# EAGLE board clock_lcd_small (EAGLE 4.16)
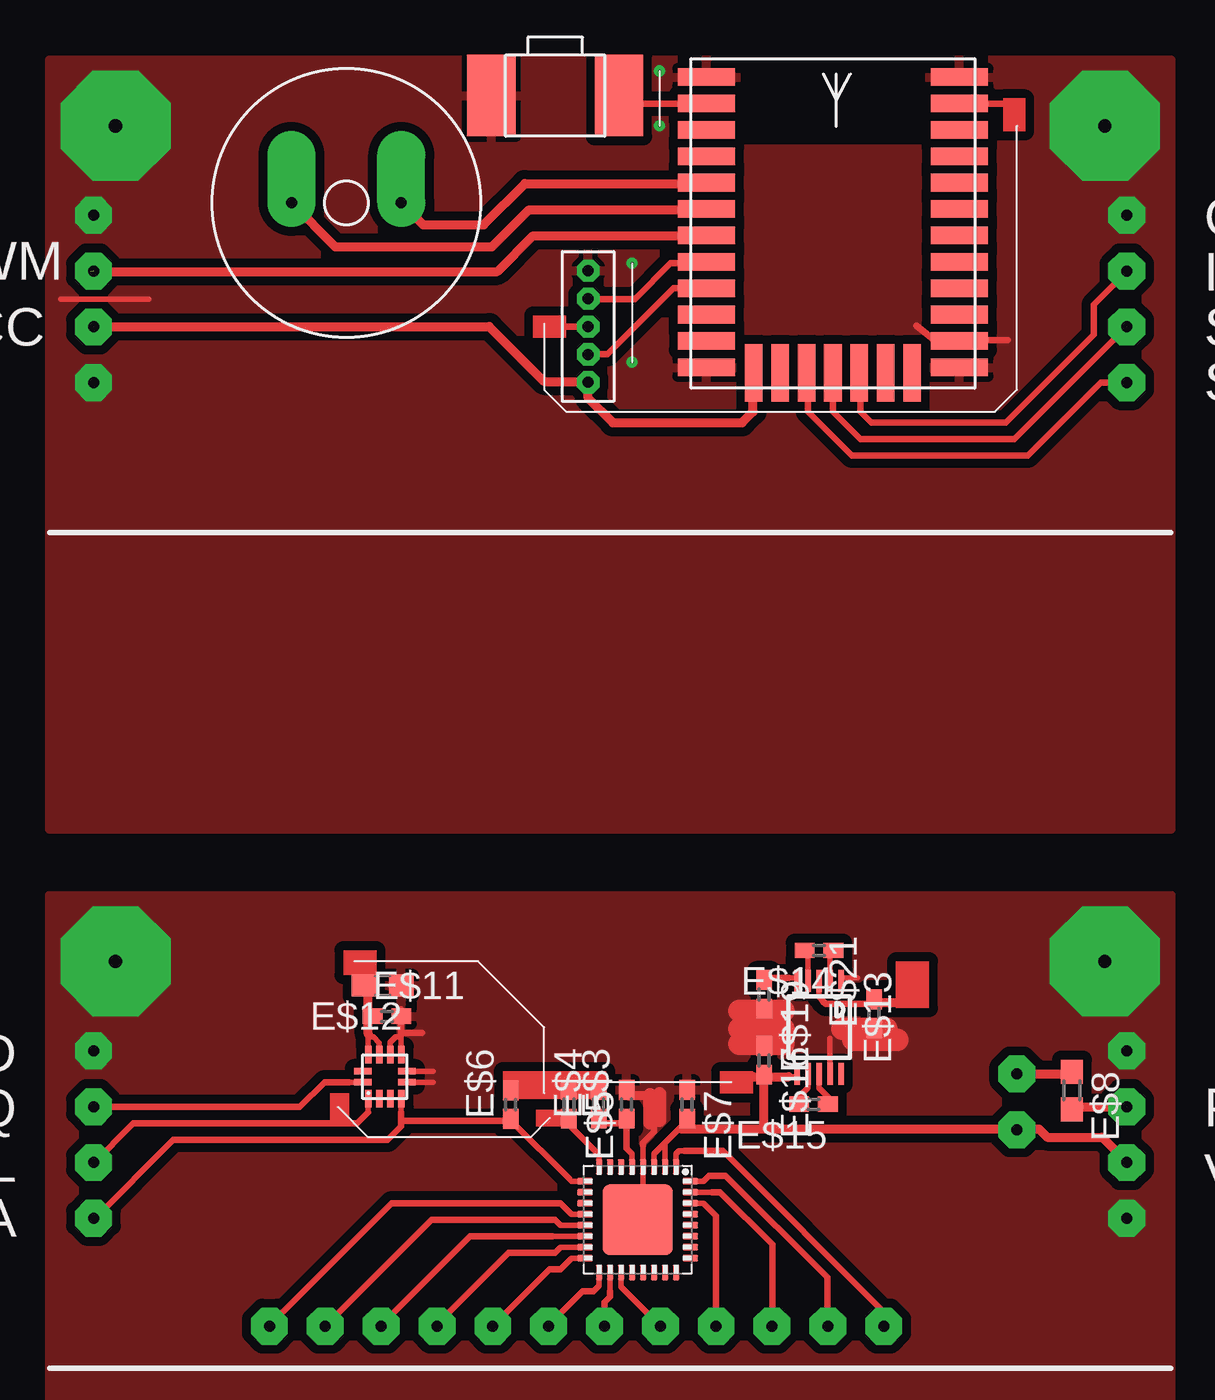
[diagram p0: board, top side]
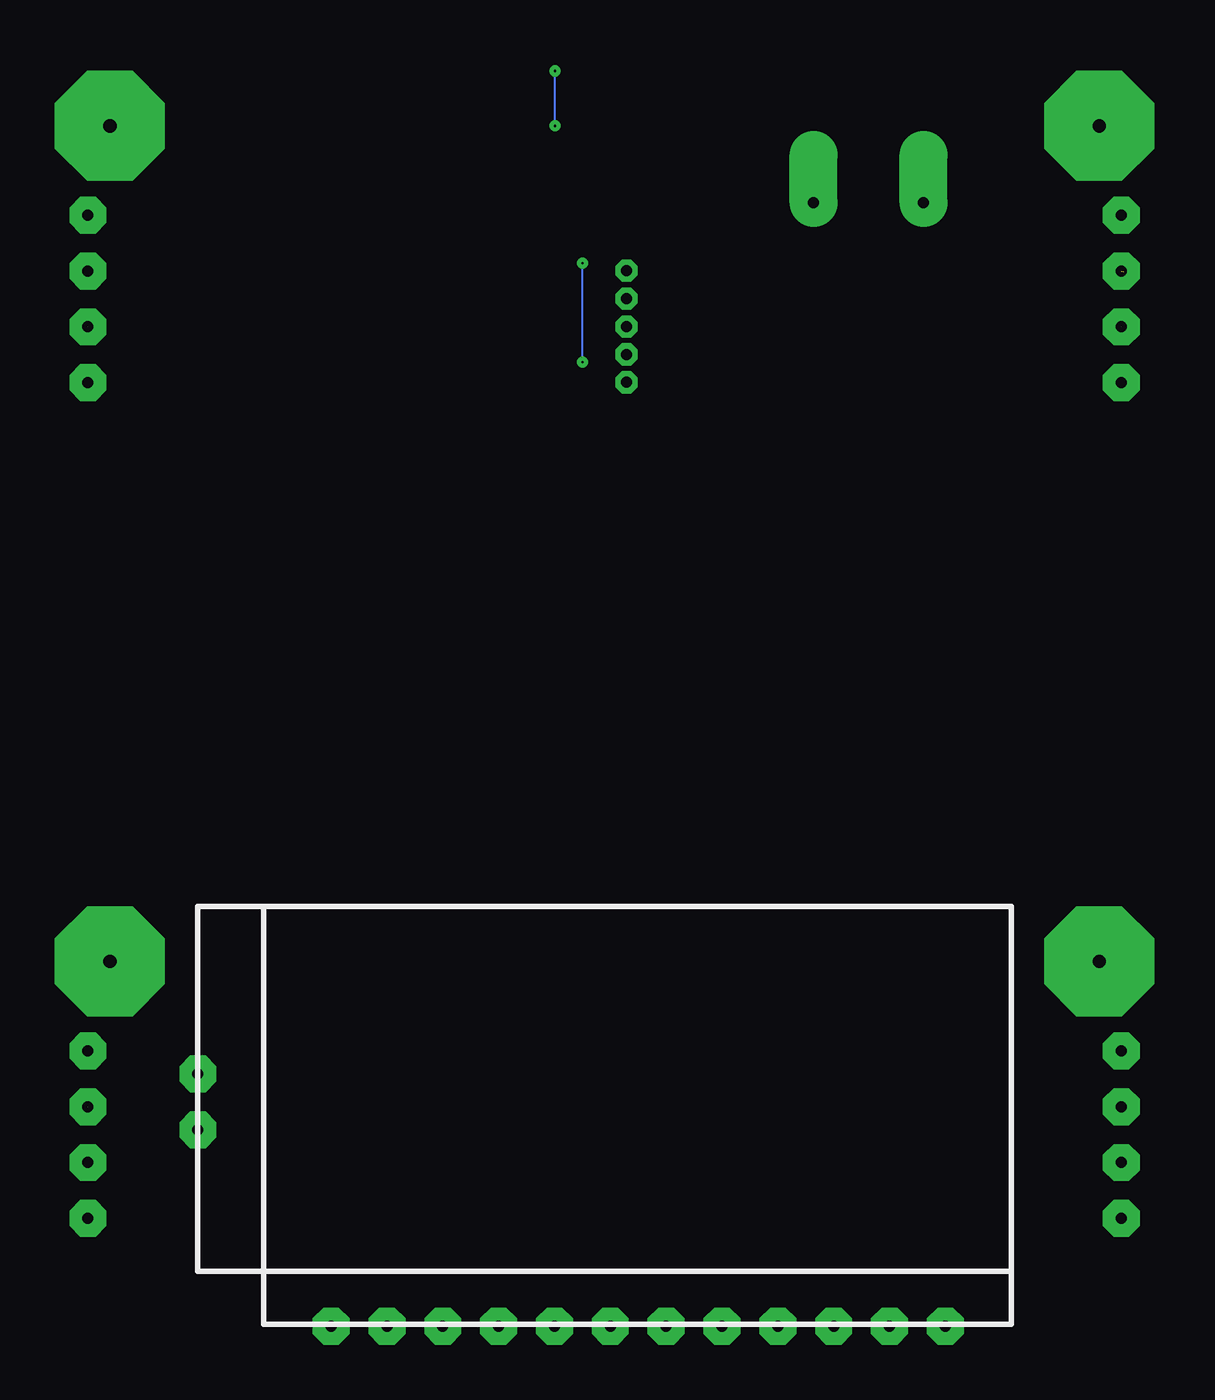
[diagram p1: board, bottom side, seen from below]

No outline drawn. Coordinates in mm, seen from the top.
Copper layers (1*16): Top 0.035mm / dielectric 1.5mm / Bottom 0.035mm
Design rules "default": minimum track width 10mil, minimum drill 24mil, track to track 8mil, track to pad 8mil, pad to pad 8mil, via to via 8mil, smd to smd 8mil, copper to edge 40mil, drill to drill 8mil, minimum pad ring 10mil, minimum via ring 8mil, stop-mask expansion 4mil, vias tented up to drill 0mil, thermal gap 10mil

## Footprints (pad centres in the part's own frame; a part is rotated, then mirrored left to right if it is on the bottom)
ALI_4D_SMALL = drill 0.5 pad 1.676 octagon: 1 3,19.09; 2 5.54,19.09; 3 8.08,19.09; 4 10.62,19.09; 5 13.16,19.09; 6 15.7,19.09; 7 18.24,19.09; 8 20.78,19.09; 9 23.32,19.09; 10 25.86,19.09; 11 28.4,19.09; 12 30.94,19.09; A 37,10.16; C 37,7.62
QFN32 = smd 0.7 x 0.3: 1 -2.15,2; 2 -2.15,1.5; 3 -2.15,1; 4 -2.15,0.5; 5 -2.15,0; 6 -2.15,-0.5; 7 -2.15,-1; 8 -2.15,-1.5; 17 2.65,-1.5; 18 2.65,-1; 19 2.65,-0.5; 20 2.65,0; 21 2.65,0.5; 22 2.65,1; 23 2.65,1.5; 24 2.65,2 | smd 0.3 x 0.7: 9 -1.5,-2.15; 10 -1,-2.15; 11 -0.5,-2.15; 12 0,-2.15; 13 0.5,-2.15; 14 1,-2.15; 15 1.5,-2.15; 16 2,-2.15; 25 2,2.65; 26 1.5,2.65; 27 1,2.65; 28 0.5,2.65; 29 0,2.65; 30 -0.5,2.65; 31 -1,2.65; 32 -1.5,2.65 | smd 3.2 x 3.2: EXP 0.25,0.25
C0402 = smd 0.9 x 0.7: 1 -0.65,0; 2 0.65,0
R0603 = smd 1.1 x 1: 1 -0.85,0; 2 0.85,0
BUZZ_12MM = drill 0.5 pad 2.184 offset: P$1 -2.5,0; P$2 2.5,0
LGA12 = smd 0.8 x 0.3: 1 -0.75,0.5; 2 -0.75,0; 3 -0.75,-0.5; 4 -0.75,-1; 7 1.25,-1; 8 1.25,-0.5; 9 1.25,0; 10 1.25,0.5 | smd 0.3 x 0.8: 5 0,-1.25; 6 0.5,-1.25; 11 0.5,0.75; 12 0,0.75
C0603 = smd 1.1 x 1: 1 -0.85,0; 2 0.85,0
MSOP10 = smd 0.25 x 1: 1 -1,-2.113; 2 -0.5,-2.113; 3 0,-2.113; 4 0.5,-2.113; 5 1,-2.113; 6 1,2.113; 7 0.5,2.113; 8 0,2.113; 9 -0.5,2.113; 10 -1,2.113
KSS = smd 2.2 x 3.7: P$1 -2.9,0; P$2 2.9,0
BGM13P = smd 2.6 x 0.8: P$1 0.7,0.95; P$2 0.7,2.15; P$3 0.7,3.35; P$4 0.7,4.55; P$5 0.7,5.75; P$6 0.7,6.95; P$7 0.7,8.15; P$8 0.7,9.35; P$9 0.7,10.55; P$10 0.7,11.75; P$11 0.7,12.95; P$12 0.7,14.15; P$13 12.2,0.95; P$14 12.2,2.15; P$15 12.2,3.35; P$16 12.2,4.55; P$17 12.2,5.75; P$18 12.2,6.95; P$19 12.2,8.15; P$20 12.2,9.35; P$21 12.2,10.55; P$22 12.2,11.75; P$23 12.2,12.95; P$24 12.2,14.15 | smd 0.8 x 2.6: P$25 2.85,0.7; P$26 4.05,0.7; P$27 5.25,0.7; P$28 6.45,0.7; P$29 7.65,0.7; P$30 8.85,0.7; P$31 10.05,0.7
HEADER5SH = drill 0.5 octagon: P$1 -2.54,0; P$2 -1.27,0; P$3 0,0; P$4 2.54,0; P$5 1.27,0

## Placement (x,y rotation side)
E$1  [ALI_4D_SMALL]  7,34.5 180 bottom
E$2  [QFN32]  26.5,20.5 270 top
E$3  [C0402]  26.25,25.5 90 top
E$4  [C0402]  24.98,25.5 90 top
E$5  [C0402]  23.62,25.5 270 top
E$6  [C0402]  20.98,25.49 90 top
E$7  [C0402]  29,25.5 270 top
E$8  [R0603]  46.5,26.12 270 top
E$9  [BUZZ_12MM]  13.5,66.5 0 top
E$10  [LGA12]  15,26.5 90 top
E$11  [C0402]  15.35,29.5 0 top
E$12  [C0603]  15.15,30.9 180 top
E$13  [MSOP10]  35,29 180 top
E$14  [C0402]  35,32.5 180 top
E$15  [C0402]  34.75,25.5 180 top
E$16  [C0402]  32.5,27.5 270 top
E$18  [KSS]  23,71.38 180 top
E$19  [C0402]  32.5,30.5 270 top
E$20  [BGM13P]  29.18,58.06 0 top
E$21  [C0402]  37.5,29.62 90 top
E$25  [HEADER5SH]  24.5,60.88 90 top

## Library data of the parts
E$1 = display-lcd
E$2 = texas
E$3-E$6 E$11 E$12 E$14-E$16 E$19 E$21 = ref-packages
E$7 E$8 = rcl
E$9 = buzzer
E$10 = st-microelectronics
E$13 = analog-devices
E$18 = switch-misc
E$20 = silabs
E$25 = sb

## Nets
GND1: E$3.2 E$7.1 E$11.2 E$12.1 E$16.1 E$19.2 E$21.1
GND4: E$18.P$2 E$20.P$1 E$20.P$12 E$20.P$13 E$20.P$24 E$25.P$4

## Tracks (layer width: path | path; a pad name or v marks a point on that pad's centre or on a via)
GND1  (via drill 0.5 pad 1.68, 0.6 pad 5)
  Top 0.254: 27,21.5 27,23.62 | 16,28.56 16,28 | 16,28.56 15.75,28.56 15.5,28.31 15.5,28 | 16,28.75 16,28.56 | 17.45,27 16.5,27 | 17.45,26.5 16.5,26.5 | 35.5,27 35.5,28.5 | 36.75,31.25 36,31.25
  Top 0.305: 27,23.62 27,23.75 27.5,24.25 27.5,24.75 | 16,28.75 16.95,28.75 | 16,29.81 16,28.81
  Top 0.406: 27.38,25.88 26.38,25.88
  Top 0.61: 27.3,24.65 27.3,25.93 | 27.75,24.76 27.75,25.98
  Top 1.016: 31.38,28.25 33.38,28.25 | 31.38,29.75 33.38,29.75 | 36.06,28.94 38.06,28.94 | 36.56,28.44 38.56,28.44 | 31.38,28.94 33.38,28.94
  other vias: 49,20.31 48,32 3,32 49,27.93 2,27.93
  pour Top (isolate 0.406): 0,0 0,35 51,35 51,0
GND4  (via drill 0.1 pad 0.1, 0.5 pad 1.68, 0.6 pad 5)
  Top 0.254: 0.5,62.12 4.5,62.12
  Top 0.305: 43.59,60.26 40.63,60.26 40.25,60.25 39.43,60.91
  Bottom 0.1: v26.5,59.25 v26.5,63.75 | v27.75,70 v27.75,72.5
  other vias: 3,70 48,70 2,65.94 2,58.32 49,65.94
  pour Top (isolate 0.406): 0,38 0,73 51,73 51,38
S$1
  Top 0.254: 25.5,17 25.5,17.5
  Top 0.305: 25.5,16.94 25.5,17 25.5,16.75 25.25,16.5 25.25,15.38
S$2
  Top 0.254: 35.5,32.5 35.5,31.5
S$3
  Top 0.254: 26.12,17.06 26,17.19 26,17.5
  Top 0.305: 26.12,17.06 27.75,15.44
S$4
  Top 0.254: 28.88,23.38 28.62,23.38 28.5,23.25 28.5,23
  Top 0.305: 28.88,23.38 30.62,23.38 38,16 38,15.38
S$5
  Top 0.254: 29.88,22.12 29.75,22 29.5,22
  Top 0.305: 29.88,22.12 30,22.25 30.75,22.25 35.38,17.62 35.38,15.38
S$6
  Top 0.254: 30.12,21.5 29.5,21.5
  Top 0.305: 30.12,21.5 30.5,21.5 32.88,19.12 32.88,15.38
S$7
  Top 0.254: 30,20.75 29.75,21 29.5,21
  Top 0.305: 30,20.75 30.31,20.44 30.31,15.31
S$8
  Top 0.254: 22.88,19.5 24,19.5
  Top 0.305: 22.88,19.5 19.12,19.5 15.12,15.5
S$9
  Top 0.254: 34.5,32.5 34.5,31.5
S$10
  Top 0.254: 23,18.75 23.25,19 24.5,19
  Top 0.305: 17.62,15.5 20.88,18.75 23,18.75
S$11
  Top 0.254: 23.25,18 23.75,18.5 24,18.5
  Top 0.305: 23.25,18 22.75,18 20.25,15.5
S$12
  Top 0.254: 24.88,17.12 25,17.25 25,17.5
  Top 0.305: 24.88,17.12 24.75,17 24.25,17 22.62,15.38
S$13
  Top 0.254: 23,20.25 23.25,20 24,20
  Top 0.305: 12.62,15.5 17.38,20.25 23,20.25
S$14
  Top 0.254: 23.62,22.12 23.75,22 24.5,22 | 16,25.12 16,25.5
  Top 0.305: 23.62,22.12 21,24.75 16,24.75 16,25.12
S$15
  Top 0.254: 23.25,21 23.75,20.5 24.5,20.5
  Top 0.305: 23.25,21 15.56,21 10,15.44
S$16
  Top 0.254: 24.88,23.31 25,23.19 25,23
  Top 0.305: 23.62,24.56 24.88,23.31
S$17
  Top 0.254: 26.5,23 26.5,23.25 26.25,23.5
  Top 0.305: 26.25,24.5 26.25,23.5
S$18
  Top 0.305: 25,24.62 26,24.62
S$19
  Top 0.254: 35,31 35,30.38 35.19,30.19
  Top 0.305: 35.19,30.19 35.31,30.06 37.38,30.06
S$20
  Top 0.254: 33.62,26.75 34,26.75
  Top 0.406: 32,26.75 33.62,26.75
S$21
  Top 0.254: 33.62,31.25 34,31.25
  Top 0.305: 32.5,31.25 33.62,31.25
S$22
  Top 0.254: 27.5,23 27.5,23.25 28,23.75 28,23
  Top 0.305: 28,23.75 29,24.75
S$23
  Top 0.406: 44,26.88 46,26.88
S$24
  Top 0.254: 14.5,28.56 14.5,28 | 14.5,28.56 14.5,28.7 | 14.5,28.56 14.74,28.56 15,28.3 15,27.5
  Top 0.406: 14.5,28.7 14.5,31.52
S$25
  Top 0.254: 13.62,26.5 14,26.5
  Top 0.305: 13.62,26.5 12.5,26.5 11.38,25.38 2,25.38
S$26
  Top 0.254: 35,26.5 35,26.25 35.5,25.75
S$27
  Top 0.254: 34.5,26.5 34.5,26.25 34,25.75
S$28
  Top 0.406: 32.5,24.5 32.5,26.5
S$29
  Top 0.406: 37.5,30.12 39,30.12
S$30
  Top 0.406: 29.19,66.19 21.81,66.19 20.12,64.5 13,64.5 11,66.5
S$31
  Top 0.406: 29.38,67.38 21.62,67.38 19.75,65.5 17,65.5 16,66.5
S$32  (via drill 0.5 pad 1.68)
  other vias: 49,22.85
S$33  (via drill 0.5 pad 1.68)
  other vias: 2,20.31
S$35
  Top 0.305: 2,20.25 5.62,23.88 15.38,23.88 16,24.5 16,25
S$36  (via drill 0.5 pad 1.68)
  other vias: 2,22.85
S$37
  Top 0.254: 14.5,25.12 14.5,25.5
  Top 0.305: 1.94,22.75 3.81,24.62 14,24.62 14.5,25.12
S$38  (via drill 0.5 pad 1.68)
  other vias: 2,25.39
S$39
  Top 0.406: 28.75,24.38 45,24.38 45.38,24 47.88,24 49,22.88
S$40  (via drill 0.5 pad 1.68)  (1 unrouted)
  Top 0.406: 46.38,25.38 49,25.38
  other vias: 49,25.39
S$42
  Top 0.305: 49,63.38 47.5,61.88 47.5,60.5 43.5,56.5 37.38,56.5 36.88,57 36.88,58.5
S$43
  Top 0.406: 32,58 32,57 31.5,56.5 25.62,56.5 24.5,57.62 24.5,58.38
S$44  (via drill 0.5 pad 1.68)  (1 unrouted)
  Top 0.406: 1.88,63.38 20.38,63.38 22,65 29.12,65
  other vias: 2,63.4
S$46  (via drill 0.5 pad 1.68)
  other vias: 49,63.4
S$67
  Top 0.305: 25.5,71 29.5,71
S$68
  Top 0.305: 24.5,62.12 26.62,62.12 28.25,63.75 29.12,63.75
S$70
  Top 0.305: 24.5,59.62 25.38,59.62 28.38,62.62 29.12,62.62
S$76
  Top 0.305: 42,71 44,71
S$77  (via drill 0.5 pad 1.68)
  other vias: 49,58.32
S$78
  Top 0.305: 23,60.88 24.5,60.88
S$95  (via drill 0.5 pad 1.68)  (1 unrouted)
  Top 0.305: 35.62,58.5 35.62,57 36.88,55.75 43.88,55.75 49,60.88
  other vias: 49,60.86
S$96  (via drill 0.5 pad 1.68)  (1 unrouted)
  Top 0.406: 2,60.88 20,60.88 22.5,58.38 24.5,58.38
  other vias: 2,60.86
S$97
  Top 0.305: 34.5,58 34.5,57 36.5,55 44.5,55 47.81,58.31 49.06,58.31
(copper drawn outside any net)
  shapes: Top area x8

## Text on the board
tPlace: GND | PWM | IRQ | VCC | SCL | SDA | GND | IRQ | SCL | PWM | VCC | SDA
